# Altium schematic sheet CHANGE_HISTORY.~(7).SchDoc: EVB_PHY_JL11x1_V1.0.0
size A4; Revision: V1.0.0; SheetNumber: 1; SheetTotal: 3; Release Date: 2014-05-28; SchModifyDate: 2020.11.1; PCBVersion: V1.0.0; PCBPartNumber: EVB_PHY_SZ18201; 版本号: V1.0.0
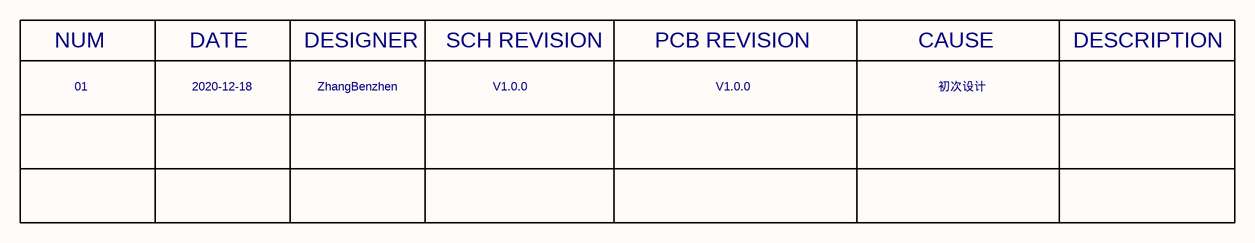
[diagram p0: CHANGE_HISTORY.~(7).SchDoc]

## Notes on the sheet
- NUM
- DATE
- DESIGNER
- SCH REVISION
- PCB REVISION
- CAUSE
- DESCRIPTION
- 01
- 2020-12-18
- ZhangBenzhen
- V1.0.0
- 初次设计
